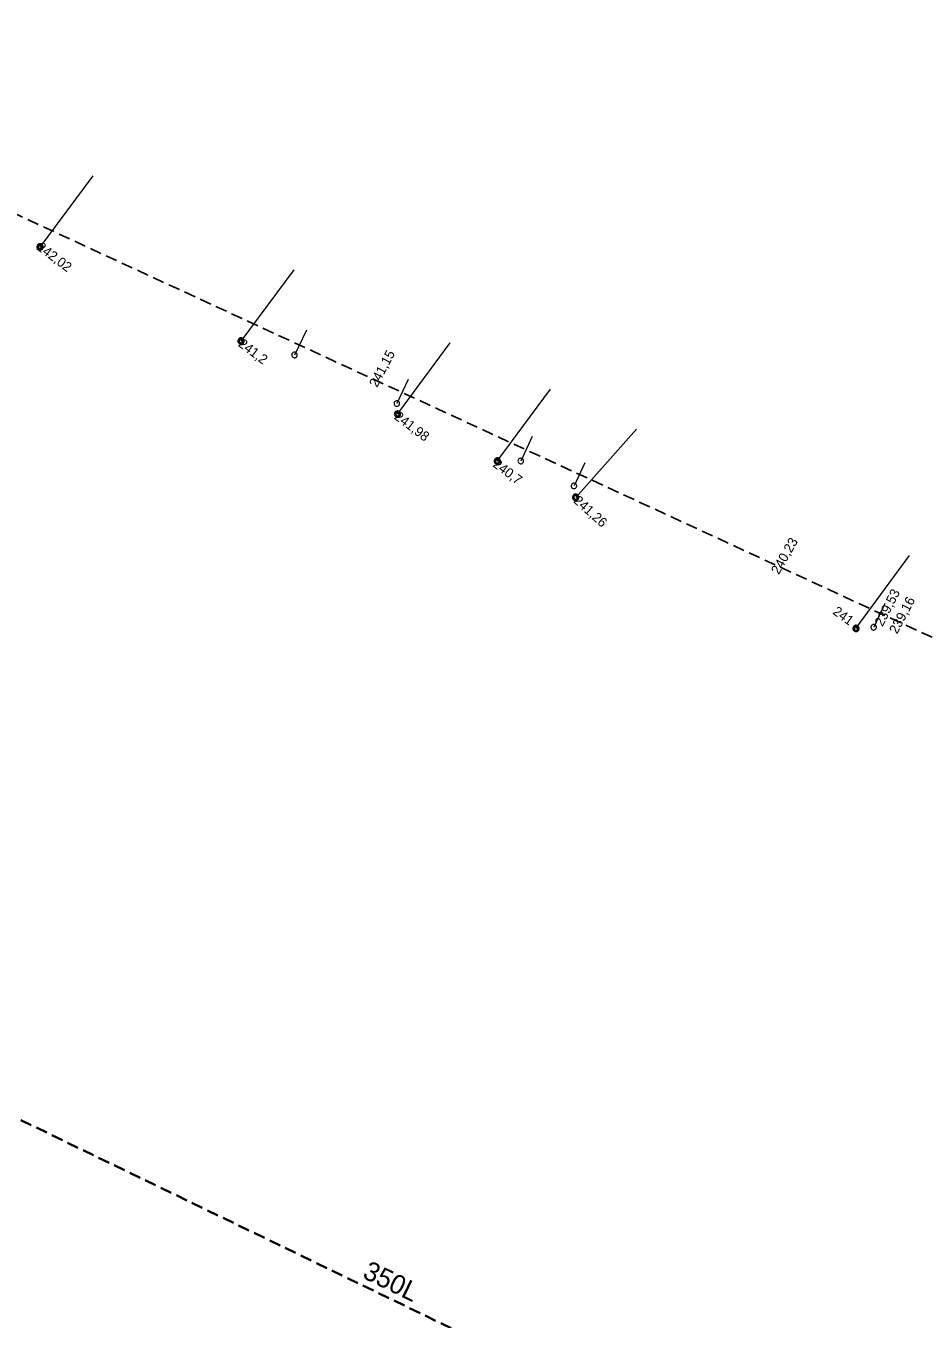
# Model space of a CAD drawing. Extents: x -735085 to -733500, y -1044153 to -1043402.
# Drawn here: x -734370.7 to -734295.8, y -1043798.1 to -1043690.4 of the extents above; entities that cross this region are included whole.
import ezdxf

# ---------------------------------------------------------------- set-up
doc = ezdxf.new("R2010")
doc.units = 0
doc.header["$LTSCALE"] = 0.32
doc.linetypes.add('MEDIUM_DASHED', pattern=[4.5, 3, -1.5])
doc.layers.add('15', color=7, linetype='Continuous')
doc.layers.add('16', color=7, linetype='Continuous')
for name, color, linetype, lineweight in [('18', 7, 'Continuous', 13), ('49', 7, 'Continuous', 13), ('63', 7, 'MEDIUM_DASHED', 25), ('8', 7, 'Continuous', 13)]:
    doc.layers.add(name, color=color, linetype=linetype, lineweight=lineweight)

msp = doc.modelspace()

# ---------------------------------------------------------------- linework, layer by layer
at = {"layer": '18'}
for points in [[(-734369.253, -1043708.778), (-734369.259, -1043708.722), (-734369.276, -1043708.669), (-734369.304, -1043708.62), (-734369.343, -1043708.579), (-734369.389, -1043708.547), (-734369.441, -1043708.525), (-734369.496, -1043708.514), (-734369.552, -1043708.516), (-734369.607, -1043708.529), (-734369.657, -1043708.554), (-734369.702, -1043708.589), (-734369.738, -1043708.632), (-734369.763, -1043708.682), (-734369.778, -1043708.737), (-734369.781, -1043708.793), (-734369.772, -1043708.848), (-734369.751, -1043708.901), (-734369.72, -1043708.947), (-734369.679, -1043708.986), (-734369.632, -1043709.016), (-734369.579, -1043709.035), (-734369.523, -1043709.042), (-734369.467, -1043709.038), (-734369.413, -1043709.021), (-734369.364, -1043708.994), (-734369.322, -1043708.956), (-734369.289, -1043708.911), (-734369.266, -1043708.86), (-734369.254, -1043708.805)], [(-734369.312, -1043708.781), (-734369.318, -1043708.732), (-734369.336, -1043708.686), (-734369.364, -1043708.645), (-734369.401, -1043708.612), (-734369.445, -1043708.59), (-734369.493, -1043708.578), (-734369.542, -1043708.578), (-734369.59, -1043708.59), (-734369.634, -1043708.613), (-734369.671, -1043708.646), (-734369.699, -1043708.687), (-734369.716, -1043708.734), (-734369.722, -1043708.783), (-734369.715, -1043708.832), (-734369.697, -1043708.878), (-734369.669, -1043708.918), (-734369.632, -1043708.951), (-734369.588, -1043708.973), (-734369.539, -1043708.985), (-734369.49, -1043708.984), (-734369.442, -1043708.972), (-734369.399, -1043708.948), (-734369.362, -1043708.915), (-734369.334, -1043708.874), (-734369.318, -1043708.827)], [(-734369.371, -1043708.785), (-734369.377, -1043708.743), (-734369.394, -1043708.705), (-734369.422, -1043708.674), (-734369.456, -1043708.651), (-734369.497, -1043708.64), (-734369.539, -1043708.64), (-734369.579, -1043708.652), (-734369.614, -1043708.675), (-734369.641, -1043708.707), (-734369.657, -1043708.745), (-734369.663, -1043708.786), (-734369.657, -1043708.828), (-734369.639, -1043708.865), (-734369.611, -1043708.897), (-734369.575, -1043708.919), (-734369.535, -1043708.93), (-734369.493, -1043708.929), (-734369.453, -1043708.916), (-734369.419, -1043708.893), (-734369.392, -1043708.86), (-734369.376, -1043708.822)], [(-734352.494, -1043716.614), (-734352.5, -1043716.558), (-734352.517, -1043716.505), (-734352.546, -1043716.456), (-734352.584, -1043716.415), (-734352.63, -1043716.383), (-734352.682, -1043716.361), (-734352.737, -1043716.35), (-734352.793, -1043716.352), (-734352.848, -1043716.365), (-734352.899, -1043716.39), (-734352.943, -1043716.425), (-734352.979, -1043716.468), (-734353.004, -1043716.518), (-734353.019, -1043716.573), (-734353.022, -1043716.629), (-734353.013, -1043716.684), (-734352.992, -1043716.737), (-734352.961, -1043716.783), (-734352.921, -1043716.822), (-734352.873, -1043716.852), (-734352.82, -1043716.871), (-734352.764, -1043716.878), (-734352.708, -1043716.874), (-734352.654, -1043716.857), (-734352.605, -1043716.83), (-734352.563, -1043716.792), (-734352.53, -1043716.747), (-734352.507, -1043716.696), (-734352.495, -1043716.641)], [(-734352.553, -1043716.617), (-734352.559, -1043716.568), (-734352.577, -1043716.522), (-734352.605, -1043716.481), (-734352.642, -1043716.448), (-734352.686, -1043716.426), (-734352.734, -1043716.414), (-734352.783, -1043716.414), (-734352.831, -1043716.426), (-734352.875, -1043716.449), (-734352.912, -1043716.482), (-734352.94, -1043716.523), (-734352.957, -1043716.57), (-734352.963, -1043716.619), (-734352.956, -1043716.668), (-734352.938, -1043716.714), (-734352.91, -1043716.754), (-734352.873, -1043716.787), (-734352.829, -1043716.809), (-734352.78, -1043716.821), (-734352.731, -1043716.82), (-734352.683, -1043716.808), (-734352.64, -1043716.784), (-734352.603, -1043716.751), (-734352.575, -1043716.71), (-734352.559, -1043716.663)], [(-734352.612, -1043716.621), (-734352.618, -1043716.579), (-734352.635, -1043716.541), (-734352.663, -1043716.51), (-734352.698, -1043716.487), (-734352.738, -1043716.476), (-734352.78, -1043716.476), (-734352.82, -1043716.488), (-734352.855, -1043716.511), (-734352.882, -1043716.543), (-734352.899, -1043716.581), (-734352.904, -1043716.622), (-734352.898, -1043716.664), (-734352.88, -1043716.701), (-734352.852, -1043716.733), (-734352.816, -1043716.755), (-734352.776, -1043716.766), (-734352.734, -1043716.765), (-734352.694, -1043716.752), (-734352.66, -1043716.729), (-734352.633, -1043716.696), (-734352.617, -1043716.658)], [(-734339.45, -1043722.713), (-734339.456, -1043722.657), (-734339.473, -1043722.604), (-734339.502, -1043722.555), (-734339.54, -1043722.514), (-734339.586, -1043722.482), (-734339.638, -1043722.46), (-734339.693, -1043722.449), (-734339.749, -1043722.451), (-734339.804, -1043722.464), (-734339.855, -1043722.489), (-734339.899, -1043722.524), (-734339.935, -1043722.567), (-734339.96, -1043722.617), (-734339.975, -1043722.672), (-734339.978, -1043722.728), (-734339.969, -1043722.783), (-734339.948, -1043722.836), (-734339.917, -1043722.882), (-734339.877, -1043722.921), (-734339.829, -1043722.951), (-734339.776, -1043722.97), (-734339.72, -1043722.977), (-734339.664, -1043722.973), (-734339.61, -1043722.956), (-734339.561, -1043722.929), (-734339.519, -1043722.891), (-734339.486, -1043722.846), (-734339.463, -1043722.795), (-734339.451, -1043722.74)], [(-734339.509, -1043722.716), (-734339.515, -1043722.667), (-734339.533, -1043722.621), (-734339.561, -1043722.58), (-734339.598, -1043722.547), (-734339.642, -1043722.525), (-734339.69, -1043722.513), (-734339.739, -1043722.513), (-734339.787, -1043722.525), (-734339.831, -1043722.548), (-734339.868, -1043722.581), (-734339.896, -1043722.622), (-734339.913, -1043722.669), (-734339.919, -1043722.718), (-734339.912, -1043722.767), (-734339.894, -1043722.813), (-734339.866, -1043722.853), (-734339.829, -1043722.886), (-734339.785, -1043722.908), (-734339.736, -1043722.92), (-734339.687, -1043722.919), (-734339.639, -1043722.907), (-734339.596, -1043722.883), (-734339.559, -1043722.85), (-734339.531, -1043722.809), (-734339.515, -1043722.762)], [(-734339.568, -1043722.72), (-734339.574, -1043722.678), (-734339.591, -1043722.64), (-734339.619, -1043722.609), (-734339.654, -1043722.586), (-734339.694, -1043722.575), (-734339.736, -1043722.575), (-734339.776, -1043722.587), (-734339.811, -1043722.61), (-734339.838, -1043722.642), (-734339.855, -1043722.68), (-734339.86, -1043722.721), (-734339.854, -1043722.763), (-734339.836, -1043722.8), (-734339.808, -1043722.832), (-734339.772, -1043722.854), (-734339.732, -1043722.865), (-734339.69, -1043722.864), (-734339.65, -1043722.851), (-734339.616, -1043722.828), (-734339.589, -1043722.795), (-734339.573, -1043722.757)], [(-734331.128, -1043726.62), (-734331.134, -1043726.564), (-734331.151, -1043726.511), (-734331.179, -1043726.462), (-734331.218, -1043726.421), (-734331.264, -1043726.389), (-734331.316, -1043726.367), (-734331.371, -1043726.356), (-734331.427, -1043726.358), (-734331.482, -1043726.371), (-734331.532, -1043726.396), (-734331.577, -1043726.431), (-734331.613, -1043726.474), (-734331.638, -1043726.524), (-734331.653, -1043726.579), (-734331.656, -1043726.635), (-734331.647, -1043726.69), (-734331.626, -1043726.743), (-734331.595, -1043726.789), (-734331.554, -1043726.828), (-734331.507, -1043726.858), (-734331.454, -1043726.877), (-734331.398, -1043726.884), (-734331.342, -1043726.88), (-734331.288, -1043726.863), (-734331.239, -1043726.836), (-734331.197, -1043726.798), (-734331.164, -1043726.753), (-734331.141, -1043726.702), (-734331.129, -1043726.647)], [(-734331.187, -1043726.623), (-734331.193, -1043726.574), (-734331.211, -1043726.528), (-734331.239, -1043726.487), (-734331.276, -1043726.454), (-734331.32, -1043726.432), (-734331.368, -1043726.42), (-734331.417, -1043726.42), (-734331.465, -1043726.432), (-734331.509, -1043726.455), (-734331.546, -1043726.488), (-734331.574, -1043726.529), (-734331.591, -1043726.576), (-734331.597, -1043726.625), (-734331.59, -1043726.674), (-734331.572, -1043726.72), (-734331.544, -1043726.76), (-734331.507, -1043726.793), (-734331.463, -1043726.815), (-734331.414, -1043726.827), (-734331.365, -1043726.826), (-734331.317, -1043726.814), (-734331.274, -1043726.79), (-734331.237, -1043726.757), (-734331.209, -1043726.716), (-734331.193, -1043726.669)], [(-734331.246, -1043726.627), (-734331.252, -1043726.585), (-734331.269, -1043726.547), (-734331.297, -1043726.516), (-734331.331, -1043726.493), (-734331.372, -1043726.482), (-734331.414, -1043726.482), (-734331.454, -1043726.494), (-734331.489, -1043726.517), (-734331.516, -1043726.549), (-734331.532, -1043726.587), (-734331.538, -1043726.628), (-734331.532, -1043726.67), (-734331.514, -1043726.707), (-734331.486, -1043726.739), (-734331.45, -1043726.761), (-734331.41, -1043726.772), (-734331.368, -1043726.771), (-734331.328, -1043726.758), (-734331.294, -1043726.735), (-734331.267, -1043726.702), (-734331.251, -1043726.664)], [(-734324.593, -1043729.644), (-734324.598, -1043729.588), (-734324.615, -1043729.535), (-734324.644, -1043729.486), (-734324.683, -1043729.445), (-734324.728, -1043729.413), (-734324.781, -1043729.391), (-734324.836, -1043729.38), (-734324.892, -1043729.382), (-734324.946, -1043729.395), (-734324.997, -1043729.42), (-734325.042, -1043729.455), (-734325.078, -1043729.498), (-734325.103, -1043729.548), (-734325.118, -1043729.603), (-734325.12, -1043729.659), (-734325.112, -1043729.714), (-734325.091, -1043729.767), (-734325.059, -1043729.813), (-734325.019, -1043729.852), (-734324.972, -1043729.882), (-734324.919, -1043729.901), (-734324.863, -1043729.908), (-734324.806, -1043729.904), (-734324.752, -1043729.887), (-734324.703, -1043729.86), (-734324.662, -1043729.822), (-734324.629, -1043729.777), (-734324.605, -1043729.726), (-734324.593, -1043729.671)], [(-734324.652, -1043729.647), (-734324.657, -1043729.598), (-734324.676, -1043729.552), (-734324.703, -1043729.511), (-734324.74, -1043729.478), (-734324.784, -1043729.456), (-734324.833, -1043729.444), (-734324.882, -1043729.444), (-734324.929, -1043729.456), (-734324.973, -1043729.479), (-734325.011, -1043729.512), (-734325.039, -1043729.553), (-734325.056, -1043729.6), (-734325.061, -1043729.649), (-734325.054, -1043729.698), (-734325.037, -1043729.744), (-734325.009, -1043729.784), (-734324.972, -1043729.817), (-734324.928, -1043729.839), (-734324.879, -1043729.851), (-734324.83, -1043729.85), (-734324.782, -1043729.838), (-734324.739, -1043729.814), (-734324.701, -1043729.781), (-734324.674, -1043729.74), (-734324.657, -1043729.693)], [(-734324.711, -1043729.651), (-734324.717, -1043729.609), (-734324.733, -1043729.571), (-734324.762, -1043729.54), (-734324.796, -1043729.517), (-734324.837, -1043729.506), (-734324.879, -1043729.506), (-734324.919, -1043729.518), (-734324.953, -1043729.541), (-734324.98, -1043729.573), (-734324.997, -1043729.611), (-734325.002, -1043729.652), (-734324.997, -1043729.694), (-734324.978, -1043729.731), (-734324.951, -1043729.763), (-734324.914, -1043729.785), (-734324.875, -1043729.796), (-734324.833, -1043729.795), (-734324.793, -1043729.782), (-734324.759, -1043729.759), (-734324.732, -1043729.726), (-734324.716, -1043729.688)], [(-734301.222, -1043740.569), (-734301.228, -1043740.513), (-734301.245, -1043740.46), (-734301.274, -1043740.411), (-734301.312, -1043740.37), (-734301.358, -1043740.338), (-734301.41, -1043740.316), (-734301.465, -1043740.305), (-734301.521, -1043740.307), (-734301.576, -1043740.32), (-734301.627, -1043740.345), (-734301.671, -1043740.38), (-734301.707, -1043740.423), (-734301.732, -1043740.473), (-734301.747, -1043740.528), (-734301.75, -1043740.584), (-734301.741, -1043740.639), (-734301.72, -1043740.692), (-734301.689, -1043740.738), (-734301.649, -1043740.777), (-734301.601, -1043740.807), (-734301.548, -1043740.826), (-734301.492, -1043740.833), (-734301.436, -1043740.829), (-734301.382, -1043740.812), (-734301.333, -1043740.785), (-734301.291, -1043740.747), (-734301.258, -1043740.702), (-734301.235, -1043740.651), (-734301.223, -1043740.596)], [(-734301.281, -1043740.572), (-734301.287, -1043740.523), (-734301.305, -1043740.477), (-734301.333, -1043740.436), (-734301.37, -1043740.403), (-734301.414, -1043740.381), (-734301.462, -1043740.369), (-734301.511, -1043740.369), (-734301.559, -1043740.381), (-734301.603, -1043740.404), (-734301.64, -1043740.437), (-734301.668, -1043740.478), (-734301.685, -1043740.525), (-734301.691, -1043740.574), (-734301.684, -1043740.623), (-734301.666, -1043740.669), (-734301.638, -1043740.709), (-734301.601, -1043740.742), (-734301.557, -1043740.764), (-734301.508, -1043740.776), (-734301.459, -1043740.775), (-734301.411, -1043740.763), (-734301.368, -1043740.739), (-734301.331, -1043740.706), (-734301.303, -1043740.665), (-734301.287, -1043740.618)], [(-734301.34, -1043740.576), (-734301.346, -1043740.534), (-734301.363, -1043740.496), (-734301.391, -1043740.465), (-734301.426, -1043740.442), (-734301.466, -1043740.431), (-734301.508, -1043740.431), (-734301.548, -1043740.443), (-734301.583, -1043740.466), (-734301.61, -1043740.498), (-734301.627, -1043740.536), (-734301.632, -1043740.577), (-734301.626, -1043740.619), (-734301.608, -1043740.656), (-734301.58, -1043740.688), (-734301.544, -1043740.71), (-734301.504, -1043740.721), (-734301.462, -1043740.72), (-734301.422, -1043740.707), (-734301.388, -1043740.684), (-734301.361, -1043740.651), (-734301.345, -1043740.613)]]:
    msp.add_lwpolyline(points, close=True, dxfattribs=at)
at = {"layer": '49'}
for p, q in [((-734369.517, -1043708.791), (-734365.087, -1043702.858)), ((-734369.517, -1043708.791), (-734365.087, -1043702.858)), ((-734352.758, -1043716.627), (-734348.329, -1043710.694)), ((-734352.758, -1043716.627), (-734348.329, -1043710.694)), ((-734339.714, -1043722.726), (-734335.315, -1043716.775)), ((-734339.714, -1043722.726), (-734335.315, -1043716.775)), ((-734331.392, -1043726.633), (-734326.965, -1043720.638)), ((-734331.392, -1043726.633), (-734326.965, -1043720.638)), ((-734324.857, -1043729.657), (-734319.796, -1043723.956)), ((-734324.857, -1043729.657), (-734319.796, -1043723.956)), ((-734301.486, -1043740.582), (-734297.017, -1043734.496)), ((-734301.486, -1043740.582), (-734297.017, -1043734.496))]:
    msp.add_line(p, q, dxfattribs=at)
at = {"layer": '63'}
msp.add_lwpolyline([(-734957.565, -1043435.501), (-734250.468, -1043761.931)], dxfattribs=at)
at = {"layer": '8'}
for p, q in [((-734347.309, -1043715.72), (-734348.29, -1043717.791)), ((-734338.82, -1043719.84), (-734339.758, -1043721.83)), ((-734328.48, -1043724.58), (-734329.426, -1043726.626)), ((-734324.1, -1043726.76), (-734324.992, -1043728.696)), ((-734299.079, -1043738.48), (-734300.002, -1043740.477))]:
    msp.add_line(p, q, dxfattribs=at)
at = {"layer": '8', "linetype": 'MEDIUM_DASHED', "lineweight": 35}
msp.add_lwpolyline([(-734536.445, -1043703.656), (-734437.539, -1043750.071), (-734375.002, -1043779.659), (-734325.456, -1043803.606), (-734187.217, -1043868.148)], dxfattribs=at)
at = {"layer": '8'}
for points in [[(-734348.201, -1043717.577), (-734348.251, -1043717.56), (-734348.304, -1043717.555), (-734348.355, -1043717.562), (-734348.405, -1043717.581), (-734348.449, -1043717.61), (-734348.484, -1043717.649), (-734348.511, -1043717.694), (-734348.526, -1043717.744), (-734348.53, -1043717.796), (-734348.522, -1043717.849), (-734348.501, -1043717.897), (-734348.471, -1043717.939), (-734348.431, -1043717.975), (-734348.386, -1043717.999), (-734348.335, -1043718.014), (-734348.283, -1043718.016), (-734348.231, -1043718.007), (-734348.182, -1043717.985), (-734348.141, -1043717.954), (-734348.107, -1043717.913), (-734348.083, -1043717.867), (-734348.07, -1043717.816), (-734348.07, -1043717.763), (-734348.081, -1043717.711), (-734348.103, -1043717.665), (-734348.135, -1043717.623), (-734348.177, -1043717.591)], [(-734339.669, -1043721.616), (-734339.719, -1043721.599), (-734339.772, -1043721.594), (-734339.823, -1043721.601), (-734339.873, -1043721.62), (-734339.916, -1043721.649), (-734339.952, -1043721.688), (-734339.979, -1043721.733), (-734339.994, -1043721.783), (-734339.998, -1043721.835), (-734339.99, -1043721.888), (-734339.969, -1043721.936), (-734339.939, -1043721.978), (-734339.9, -1043722.014), (-734339.854, -1043722.038), (-734339.803, -1043722.053), (-734339.751, -1043722.055), (-734339.699, -1043722.046), (-734339.651, -1043722.024), (-734339.609, -1043721.993), (-734339.575, -1043721.953), (-734339.551, -1043721.906), (-734339.538, -1043721.855), (-734339.538, -1043721.802), (-734339.549, -1043721.751), (-734339.571, -1043721.704), (-734339.603, -1043721.662), (-734339.645, -1043721.63)], [(-734329.338, -1043726.412), (-734329.387, -1043726.395), (-734329.44, -1043726.39), (-734329.492, -1043726.397), (-734329.542, -1043726.416), (-734329.585, -1043726.446), (-734329.621, -1043726.484), (-734329.647, -1043726.529), (-734329.663, -1043726.579), (-734329.666, -1043726.632), (-734329.657, -1043726.684), (-734329.637, -1043726.733), (-734329.607, -1043726.775), (-734329.567, -1043726.81), (-734329.521, -1043726.835), (-734329.47, -1043726.849), (-734329.418, -1043726.851), (-734329.366, -1043726.841), (-734329.318, -1043726.82), (-734329.277, -1043726.788), (-734329.243, -1043726.748), (-734329.219, -1043726.702), (-734329.206, -1043726.65), (-734329.206, -1043726.597), (-734329.217, -1043726.546), (-734329.239, -1043726.499), (-734329.272, -1043726.458), (-734329.313, -1043726.425)], [(-734324.904, -1043728.481), (-734324.954, -1043728.465), (-734325.007, -1043728.46), (-734325.058, -1043728.467), (-734325.108, -1043728.486), (-734325.151, -1043728.516), (-734325.187, -1043728.554), (-734325.213, -1043728.6), (-734325.229, -1043728.65), (-734325.232, -1043728.702), (-734325.223, -1043728.755), (-734325.203, -1043728.803), (-734325.173, -1043728.845), (-734325.133, -1043728.88), (-734325.087, -1043728.905), (-734325.036, -1043728.919), (-734324.984, -1043728.921), (-734324.932, -1043728.911), (-734324.884, -1043728.89), (-734324.843, -1043728.858), (-734324.808, -1043728.818), (-734324.785, -1043728.771), (-734324.772, -1043728.72), (-734324.772, -1043728.667), (-734324.783, -1043728.616), (-734324.806, -1043728.569), (-734324.838, -1043728.527), (-734324.879, -1043728.495)], [(-734299.914, -1043740.263), (-734299.963, -1043740.246), (-734300.016, -1043740.241), (-734300.068, -1043740.248), (-734300.118, -1043740.267), (-734300.161, -1043740.297), (-734300.197, -1043740.335), (-734300.223, -1043740.38), (-734300.239, -1043740.43), (-734300.242, -1043740.483), (-734300.233, -1043740.535), (-734300.213, -1043740.583), (-734300.183, -1043740.626), (-734300.143, -1043740.661), (-734300.097, -1043740.686), (-734300.047, -1043740.7), (-734299.994, -1043740.702), (-734299.942, -1043740.692), (-734299.894, -1043740.671), (-734299.853, -1043740.639), (-734299.819, -1043740.599), (-734299.795, -1043740.553), (-734299.782, -1043740.501), (-734299.782, -1043740.448), (-734299.793, -1043740.397), (-734299.815, -1043740.35), (-734299.848, -1043740.309), (-734299.889, -1043740.276)]]:
    msp.add_lwpolyline(points, close=True, dxfattribs=at)

# ---------------------------------------------------------------- texts
at = {"layer": '15'}
msp.add_text('350L', height=1.6, rotation=334, dxfattribs=at).set_placement((-734342.715, -1043794.639))
at = {"layer": '16'}
for s, rotation, p in [('242,02', 323, (-734369.861, -1043708.942)), ('241,2 ', 323, (-734353.057, -1043716.997)), ('241,15', 62, (-734341.422, -1043720.54)), ('241,98', 323, (-734340.049, -1043723.06)), ('240,7 ', 323, (-734331.835, -1043727.026)), ('241,26', 318, (-734325.102, -1043730.012)), ('240,23', 60, (-734307.927, -1043736.132)), ('239,53', 63, (-734299.271, -1043740.46)), ('239,16', 62, (-734298.064, -1043741.088)), ('241 ', 324, (-734303.489, -1043739.311))]:
    msp.add_text(s, height=0.8, rotation=rotation, dxfattribs=at).set_placement(p)

doc.saveas('drawing.dxf')
